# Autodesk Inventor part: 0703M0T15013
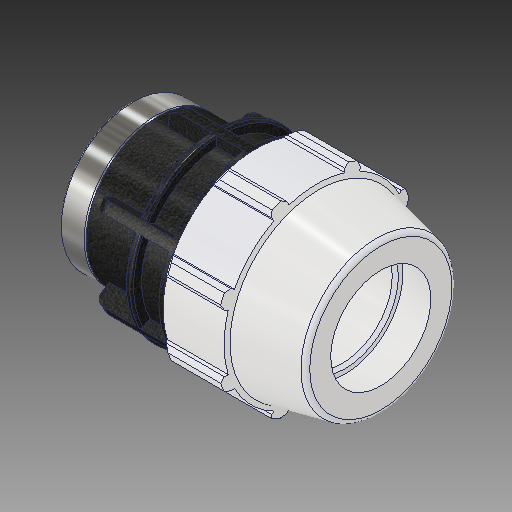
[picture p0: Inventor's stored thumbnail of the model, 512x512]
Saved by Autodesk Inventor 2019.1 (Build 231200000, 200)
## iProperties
Created: 2017-02
Part Number: 0703M0T15013
Material: PVC-Piping
Description: PLASSON FEMALE ADAPTOR G 1 1/2'' - 1 1/4''F
Document SubType Name: Modeling
Designer: KIM
Mass: 92.6774 g
Surface Area: 199.44 cm^2
Volume: 66.1981 cm^3
Density: 1.4 g/cm^3
Appearance: PTFE
Author: KIM
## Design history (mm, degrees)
derived "0703M0T.ipt"
feature "Solid1::0703M0T.ipt"
tag "TaggingFeature1"
body "Solid1"
other parameters: "d2" = 48.1, "d4" = 17.12686, "d5" = 29.972, "d7" = 96.012, "d9" = 17.12686, "d11" = 3.42537, "d12" = 76.8096, "d13" = 120 deg, "d14" = 72.15, "d15" = 12 deg, "d16" = 86.4108, "d18" = 2.405, "d19" = 35 deg, "d20" = 17.5 deg, "d21" = 89.29116, "d23" = 0, "d25" = 360 deg, "d27" = 1.92024, "d34" = 4.8006, "d35" = 35.9664, "d36" = 0, "d42" = 29.972, "d43" = 2.88036, "d46" = 1.443, "d49" = 88.9, "d51" = 119.888, "d53" = 0.962, "d55" = 360 deg, "d61" = 24.892, "d62" = 45.695, "d63" = 38.952, "d64" = 39.96267, "d65" = 4.8006, "d66" = 0.5, "d67" = 1, "d68" = 12.446, "d69" = 69.12864, "d70" = 1.27, "d_" = 48.1, "E_" = 96.012, "H_" = 119.888, "l_" = 88.9, "l_2" = 24.892, "G_" = 38.952
